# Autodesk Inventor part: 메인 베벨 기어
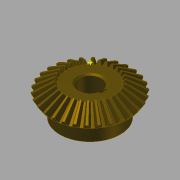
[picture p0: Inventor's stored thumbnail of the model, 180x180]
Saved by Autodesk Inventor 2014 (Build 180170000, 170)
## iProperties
Created: 2014-10
Part Number: 메인 베벨 기어
Material: 강철, 탄소
Document SubType Name: Modeling
Designer: KYOUNG IL JANG
Categories: <?xml version="1.0" encoding="UTF-16"?> <MemberInstance><Categories><FamilyTemplate><FamilyTemplateParameter ValueType="xs:double" Id="1" ObjectReferenceKey="da
Mass: 269.926 g
Surface Area: 108.837 cm^2
Volume: 34.2981 cm^3
Density: 7.87 g/cm^3
Appearance: Brindle
CustomPartVersion: 1
Author: SeoGD™ [www.esajin.kr]
Revision Number: 1
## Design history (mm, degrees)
node "맨 위 점"
node "메쉬 평면2"
sketch "톱니 본체 스케치"
  geometry: L1 (0, 0)-(28.669, -21.997); L2 (28.669, -21.997)-(31.109, -18.336); L3 (31.109, -18.336)-(0, 0); L4 (30, -20)-(0, 0); L5 (17.219, -13.212)-(18.685, -11.013); L6 (28.669, -21.997)-(17.219, -13.212); L7 (31.109, -18.336)-(18.685, -11.013); L8 (0, -39.387)-(0, 6.564) reference; L9 (0, -20)-(31.109, -20)
  constraints: 16 end point, 4 point on line, 3 perpendicular, 2 collinear, 1 horizontal alignment, 1 vertical alignment
  dimensions: "d0" = 60 diameter of L4.start L8 (= da_de); "d1" = 57.33744 diameter of L1.end L8 (= da_dfe); "d2" = 62.2188 diameter of L2.end L8 (= da_dae); "d3" = 14.4 distance between parallel lines of L2 L5 (= da_b); "d4" = 18.3359 vertical distance of L2.end L1.start (= da_ve)
revolve "톱니 본체" sketch "톱니 본체 스케치" stored, may be unused: angle "d5" = 90 deg
node "시작점"
node "톱니 평면"
sketch "시작 스케치"
  geometry: L1 (0, -23.505)-(0, 10.645) reference; L2 (-0.709, -2.928)-(0.709, -2.928); A1 r 19.188 centre (-19.457, -7.014) between (-0.709, -2.928) and (-3.232, 3.229); A2 r 19.188 centre (19.457, -7.014) between (3.232, 3.229) and (0.709, -2.928); A3 r 57.403 centre (0, -54.083) between (3.232, 3.229) and (-3.232, 3.229); 1 further point
  constraints: 6 point on circle, 3 centre point, 3 symmetric about line, 2 end point, 1 coincident, 1 perpendicular, 1 other
  dimensions: "d7" = 19.18795 radius of A1 (= fd_rr); "d8" = 19.45712 horizontal distance of point (0, -54.083) A1.centre (= fd_x); "d9" = 47.06905 vertical distance of point (0, -54.083) A1.centre (= fd_y); "d57" = 57.40327 radius of A3 (= 0.5 x fd_dva + 0.3 x da_he); "d58" = 51.15527 distance from line of A3.centre L2 (= 0.5 x fd_dva - 1.12 x da_he)
node "끝점"
  node "끝 평면"
sketch "3D 스케치 오른쪽"
  node "Helical Curve Right" dims "d65" = 229.90621 (computed from da_dm, da_delta, da_beta), "d66" = 31.5, "d67" = 60 (= da_de), "d68" = -9.82794 (= -da_delta), "d69" = 8.10972 (computed from fd_loft, da_delta)
node "끝 평면 오른쪽"
sketch "끝 스케치 오른쪽"
  geometry: L1 (0, -41.54)-(0, 13.178) reference; L2 (-0.422, -1.69)-(0.422, -1.69); A1 r 11.427 centre (-11.587, -4.123) between (-0.422, -1.69) and (-1.925, 1.977); A2 r 11.427 centre (11.587, -4.123) between (1.925, 1.977) and (0.422, -1.69); A3 r 34.184 centre (0, -32.153) between (1.925, 1.977) and (-1.925, 1.977); 1 further point
  constraints: 6 point on circle, 3 centre point, 3 symmetric about line, 2 end point, 1 coincident, 1 perpendicular, 1 other
  dimensions: "d70" = 11.58699 horizontal distance of A3.centre A1.centre (computed from fd_x, fd_ratio); "d71" = 28.03028 vertical distance of point (0, -32.153) A1.centre (computed from fd_y, fd_ratio); "d72" = 11.4267 radius of A1 (computed from fd_rr, fd_ratio); "d73" = 30.46369 distance from line of point (0, -32.153) L2 (computed from d58, fd_ratio); "d74" = 34.18446 radius of A3 (computed from d57, fd_ratio)
feature "로프트 오른쪽" sketch "끝 스케치 오른쪽" dims "d75" = 0, "d77" = 0, "d79" = 0, "d80" = 90 deg, "d85" = 20, "d92" = 90 deg, "d93" = 90 deg, "da_teethtype" = 0 [user parameter]
sketch "3D 스케치 왼쪽"
  node "Helical Curve Left" dims "d26" = 229.90621 (computed from da_dm, da_delta, da_beta), "d27" = 8.10972 (computed from fd_loft, da_delta), "d28" = 60 (= da_de), "d29" = -9.82794 (= -da_delta)
node "끝 평면 왼쪽"
sketch "끝 스케치 왼쪽" dims "d56" = 10.3728 (derived)
  geometry: L1 (0, -43.753)-(0, 15.405) reference; L2 (-0.422, -1.678)-(0.422, -1.678); A1 r 11.427 centre (-11.587, -4.111) between (-0.422, -1.678) and (-1.925, 1.988); A2 r 11.427 centre (11.587, -4.111) between (1.925, 1.988) and (0.422, -1.678); A3 r 34.184 centre (0, -32.142) between (1.925, 1.988) and (-1.925, 1.988); 2 further points; 1 other entity
  constraints: 6 point on circle, 3 centre point, 3 symmetric about line, 2 end point, 1 coincident, 2 other
  dimensions: "d30" = 11.4267 radius of A1 (computed from fd_rr, fd_ratio); "d31" = 11.58699 horizontal distance of point (0, -32.142) A1.centre (computed from fd_x, fd_ratio); "d32" = 28.03028 vertical distance of A1.centre point (0, -32.142) (computed from fd_y, fd_ratio); "d61" = 34.18446 radius of A3 (computed from d57, fd_ratio); "d62" = 30.46369 distance from line of point (0, -32.142) L2 (computed from d58, fd_ratio)
feature "로프트 왼쪽" sketch "끝 스케치 왼쪽" dims "d35" = 0, "d37" = 0, "d39" = 0, "d40" = 90 deg, "d84" = 10, "d90" = 90 deg, "d91" = 90 deg, "da_teethtype" = 0 [user parameter]
sketch "본체 스케치"
  geometry: L1 (0, -35.038)-(0, -19.531) reference; L2 (28.669, -21.997)-(17.219, -13.212) reference; L3 (17.219, -13.212)-(0, -13.212); L4 (28.669, -21.997)-(0, -21.997)
  constraints: 4 end point, 2 perpendicular, 2 point on line
revolve "본체 고정" sketch "본체 스케치" stored, may be unused: angle "d46" = 90 deg
feature "피치 지름" dims angle "d47" = 90 deg
sketch "스케치8"
  geometry: C1 r 22.5 at (0, 0); 1 further point
  constraints: 1 centre point, 1 coincident
  dimensions: "d94" = 45 diameter of C1
extrude "돌출1" join sketch "스케치8" distance "d95" = 13; taper "d96" = 0 deg
sketch "스케치9"
  geometry: 1 further point
hole "구멍1" sketch "스케치9" at (0, 0) diameter "d97" = 17; stored, may be unused: countersink angle "d101" = 90 deg, drill point angle "d103" = 118 deg; dims "d98" = 6, "d99" = 4, "d100" = 2, "d102" = 8
sketch "스케치10"
  geometry: L1 (8.124, 2.5)-(10.8, 2.5); L2 (10.8, 2.5)-(10.8, -2.5); L3 (10.8, -2.5)-(8.124, -2.5); A1 r 8.5 centre (0, 0) between (8.124, 2.5) and (8.124, -2.5) reference; 1 further point
  constraints: 6 end point, 2 parallel, 2 point on circle, 1 horizontal, 1 perpendicular
  dimensions: "d104" = 5 distance of L1.end L2.end; "d112" = 19.3 dimension on A1 L2
extrude "돌출2" cut sketch "스케치10" stored distance "d106" = 10; taper "d107" = 0 deg
chamfer "모따기1" distance "d108" = 1; stored, may be unused: second distance "d109" = 2, angle "d110" = 45 deg
fillet "모깎기1" dims "d111" = 2
body "Solid1"
feature "로프트" dims "d17" = 0, "d18" = 90 deg, "d19" = 0, "d20" = 90 deg, "d89" = 0, "da_teethtype" = 0 [user parameter]
pattern_circular "원형 패턴" dims angle "d22" = 360 deg, "d88" = 0, "da_teethtype" = 0 [user parameter]
pattern_circular "원형 패턴 오른쪽" dims angle "d82" = 360 deg, "da_teethtype" = 0 [user parameter]
pattern_circular "원형 패턴 왼쪽" dims angle "d42" = 360 deg, "da_teethtype" = 0 [user parameter]
sketch "끝 스케치"
  geometry: L1 (0, -15.359)-(0, 6.983) reference; L2 (-0.422, -1.69)-(0.422, -1.69); A1 r 11.427 centre (-11.587, -4.123) between (-0.422, -1.69) and (-1.925, 1.977); A2 r 11.427 centre (11.587, -4.123) between (1.925, 1.977) and (0.422, -1.69); A3 r 34.184 centre (0, -32.153) between (1.925, 1.977) and (-1.925, 1.977); 1 further point
  constraints: 6 point on circle, 3 centre point, 3 symmetric about line, 2 end point, 1 coincident, 1 other
  dimensions: "d12" = 11.4267 radius of A1 (computed from fd_rr, fd_ratio); "d15" = 11.58699 horizontal distance of A1.centre point (0, -32.153) (computed from fd_x, fd_ratio); "d16" = 28.03028 vertical distance of A1.centre point (0, -32.153) (computed from fd_y, fd_ratio); "d59" = 34.18446 radius of A3 (computed from d57, fd_ratio); "d60" = 30.46369 distance from line of A3.centre L2 (computed from d58, fd_ratio)
sketch "Sketch6"
  geometry: L1 (30, -20)-(0, 0) reference; L2 (0, -37.8)-(0, 6.3) reference
body "Srf1"
other parameters: "da_b" = 14.4 [user parameter; used in 2 equation terms], "da_de" = 60 [user parameter; used in 4 equation terms], "da_dae" = 62.2188 [user parameter; used in 2 equation terms], "da_dfe" = 57.33744 [user parameter; used in 1 equation term], "da_le" = 36.05551 [user parameter; used in 1 equation term], "da_omega" = 90 deg [user parameter; used in 1 equation term], "da_beta" = 0 [user parameter; used in 2 equation terms], "da_delta" = 9.82794 [user parameter; used in 8 equation terms], "da_alpha" = 20 deg [user parameter; used in 2 equation terms], "da_he" = 4.4 [user parameter; used in 4 equation terms], "da_ve" = 18.3359 [user parameter; used in 1 equation term], "fd_dv" = 108.16654 (computed from da_de, da_delta) [user parameter; used in 1 equation term], "fd_dva" = 112.16654 (computed from da_dae, da_delta) [user parameter; used in 3 equation terms], "fd_dvb" = 101.6433 (computed from fd_dv, da_alpha) [user parameter; used in 2 equation terms], "da_zv" = 540.83269 [user parameter; used in 1 equation term], "fd_loft" = 14.62 (= da_b + 0.05 x da_he) [user parameter; used in 4 equation terms], "fd_ratio" = 5.95514 (computed from da_le, fd_loft) [user parameter; used in 15 equation terms], "fd_rr" = 19.18795 (computed from fd_dd, fd_dvb) [user parameter; used in 6 equation terms], "fd_angle" = 0.29367 (computed from da_zv) [user parameter; used in 4 equation terms], "fd_x1" = 1.58802 (computed from da_dvw, fd_angle) [user parameter; used in 1 equation term], "fd_y1" = 54.05995 (computed from da_dvw, fd_angle) [user parameter; used in 1 equation term], "fd_x2" = 17.8691 (computed from fd_rr, fd_angle2, fd_angle) [user parameter; used in 1 equation term], "fd_y2" = 6.9909 (computed from fd_rr, fd_angle2, fd_angle) [user parameter; used in 1 equation term], "fd_x" = 19.45712 (= fd_x1 + fd_x2) [user parameter; used in 4 equation terms], "fd_y" = 47.06905 (= fd_y1 - fd_y2) [user parameter; used in 4 equation terms], "fd_angle2" = 3.43555 (computed from fd_dvb, fd_dd, da_alpha) [user parameter; used in 2 equation terms], "fd_dd" = 108.64654 (= fd_dva - 0.8 x da_he) [user parameter; used in 2 equation terms], "da_dvw" = 108.16654 [user parameter; used in 2 equation terms], "d11" = 14.62 (= fd_loft), "da_dm" = 48.01848 [user parameter; used in 2 equation terms], "da_x" = 0 [user parameter], "da_m" = 2 [user parameter], "d48" = 0, "d49" = 0, "d50" = 90 deg (= da_omega), "d51" = 6 deg (computed from da_z), "d52" = 0, "d53" = 0, "d54" = 0
